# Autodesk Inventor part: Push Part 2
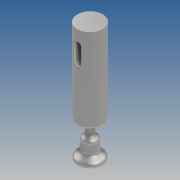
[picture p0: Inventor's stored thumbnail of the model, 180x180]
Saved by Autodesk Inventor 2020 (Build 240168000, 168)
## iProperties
Created: 2019-10
Part Number: Push Part 2
Material: Generic
Document SubType Name: Modeling
Designer: yello
Density: 1 g/cm^3
Appearance: Default
Author: yello
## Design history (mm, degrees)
sketch "Sketch2" dims "d4" = 3
  geometry: L1 (0, 0)-(2, 0); L2 (0, 0)-(0, -26); L3 (0, -26)-(2.5, -26); L4 (2.5, -26)-(2.5, -24); L5 (2.5, -24)-(3.5, -24); L6 (0, -26)-(0, -28); L7 (0, -28)-(2, -28); L8 (2, -24)-(2, 0); L9 (0, -28)-(0, -32.5); L10 (2, -28)-(2, -30); L11 (0, -32.5)-(2, -32.5); L12 (2, -32.5)-(2, -30); L13 (2, -28)-(2, -27.177); L14 (2, -27.177)-(1, -27.177); L15 (1, -27.177)-(1, -26); L16 (2, -24)-(2, -24.823); L17 (2, -24.823)-(1, -24.823); L18 (1, -24.823)-(1, -26); L19 (2, -30.25)-(2, -32.75); L20 (3.5, -32.5)-(3.5, -32.75); L21 (3.5, -32.75)-(2, -32.75); L22 (2, -32.75)-(0, -32.75); L23 (0, -32.75)-(0, -32.5); L24 (2, -30.25)-(2, -32.5); L25 (2, -30.25)-(2, -31.375); L26 (2, -31.375)-(3.5, -31.375); L27 (3.5, -31.375)-(3.5, -32.5); L28 (2, -24)-(2, -23); L29 (2, 0)-(3.5, 0); L30 (3.5, 0)-(3.5, -23.002); L31 (2, -24)-(2, -23.5); L32 (2, -23.5)-(3.5, -23.501); L33 (3.5, -23.501)-(3.5, -23.002)
  constraints: 42 end point, 9 perpendicular, 6 point on line, 6 vertical, 5 horizontal, 3 symmetric about line, 2 midpoint, 1 coincident, 1 horizontal alignment, 14 other
  dimensions: "d0" = 2 distance of L1.start L1.end; "d2" = 26 distance of L1.start L2.end; "d7" = 2 distance of L4.start L4.end; "d8" = 1.5 distance of L5.end L8.start; "d9" = 4.5 distance of L6.end L9.end; "d10" = 2 distance of L7.end L10.end; "d11" = 2.5 distance of L2.end L3.end; "d13" = 2.5 distance of L19.start L19.end; "d15" = 1 distance of L8.start L28.end; "d16" = 1.5 distance of L1.end L29.end; "d25" = 4 distance from line of L10.end L3; "d30" = 0.25 distance from line of L11 L19.end
revolve "Revolution1" sketch "Sketch2" stored, may be unused: angle "d17" = 90 deg
workplane "Work Plane1"
sketch "Sketch3"
  geometry: L1 (0, 0)-(0, -4); L2 (0, -4)-(0, -8); L3 (-1, -4)-(-1, -8); L4 (1, -8)-(1, -4); C1 r 1 at (0, -4); A1 r 1 centre (0, -4) between (1, -4) and (-1, -4); A2 r 1 centre (0, -8) between (-1, -8) and (1, -8); 3 further points
  constraints: 10 end point, 4 point on circle, 4 tangent, 3 centre point, 2 vertical, 1 coincident, 1 concentric, 1 midpoint, 1 parallel
  dimensions: "d19" = 4 distance of L1.start L1.end; "d20" = 2 diameter of C1; "d26" = 4 distance of L2.start L2.end
extrude "Extrusion2" cut sketch "Sketch3" distance "d27" = 10; taper "d28" = 0 deg
body "Solid1"
other parameters: "d18" = 3.5
